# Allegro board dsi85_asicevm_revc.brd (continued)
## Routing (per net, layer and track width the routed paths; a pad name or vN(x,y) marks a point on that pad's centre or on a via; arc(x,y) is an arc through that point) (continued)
DSI_A0P: length 41.7
  TOP w0.076: U1.H3 36.55,45.15 36.55,44.77 36.44,44.66 36.44,44.27
  TOP w0.127: 36.44,44.27 35.77,43.61 34.85,42.68 34.85,41.36 33.8,40.31 29.96,40.31 29.4,40.88 29.4,41.85 28.99,42.26 28.41,42.26 28,41.85 28,40.88 27.43,40.31 26.66,40.31 23.22,43.75 23.22,44.55 23.86,45.19 23.86,45.77 23.46,46.18 22.88,46.18 22.23,45.53 21.43,45.53 20.87,46.1 20.87,46.9 21.51,47.54 21.51,48.2 21.18,48.53 20.52,48.53 19.88,47.89 19.08,47.89 15.49,51.48 12.28,51.48 12.17,51.37 J4.33
  vias: v2(12.18,51.37)
DSI_A1N: length 42.4
  TOP w0.076: U1.J4 36.8,43.63
  TOP w0.127: J4.27 12.15,48.87 12.27,48.75 13.58,48.75 13.76,48.57 13.87,48.57 13.9,48.59 14,48.59 14.08,48.52 14.08,48.41 14.05,48.39 14.05,48.28 14.12,48.21 14.23,48.21 14.26,48.23 14.36,48.23 14.43,48.16 14.43,48.05 14.41,48.03 14.41,47.92 14.48,47.85 14.59,47.85 14.61,47.88 14.72,47.88 14.79,47.8 14.79,47.7 14.77,47.67 14.77,47.56 14.84,47.49 14.95,47.49 14.97,47.52 15.08,47.52 15.15,47.44 15.15,47.34 15.13,47.31 15.13,47.2 15.2,47.13 15.31,47.13 15.33,47.16 15.44,47.16 15.51,47.08 15.51,46.98 15.49,46.95 15.49,46.85 15.56,46.77 15.67,46.77 15.69,46.8 15.8,46.8 15.87,46.72 15.87,46.62 15.85,46.59 15.85,46.49 15.92,46.41 16.02,46.41 16.05,46.44 16.16,46.44 16.23,46.36 16.23,46.26 16.2,46.23 16.2,46.13 16.28,46.05 16.38,46.05 16.41,46.08 16.52,46.08 16.59,46 16.59,45.9 16.56,45.87 16.56,45.77 16.7,45.63 16.9,45.63 17.08,45.46 17.08,45.25 17.38,44.95 17.96,44.95 18.37,45.37 18.53,45.53 19.49,45.53 19.9,45.12 19.9,44.16 19.74,44 19.32,43.59 19.32,43.01 19.73,42.6 20.31,42.6 20.73,43.02 20.88,43.17 21.72,43.17 22.25,42.64 22.25,41.81 22.09,41.65 21.68,41.23 21.68,40.66 23.49,38.84 24.09,38.84 24.63,39.38 25.88,39.38 26.43,38.84 27.41,38.84 27.96,39.38 29.21,39.38 29.75,38.84 30.74,38.84 31.28,39.38 32.54,39.38 33.08,38.84 34.24,38.84 36,40.6 36,42.03 36.8,42.83 36.8,43.63
  vias: v2(12.19,48.87)
DSI_A1P: length 41.8
  TOP w0.076: 37.05,44.22 37.05,45.15 U1.H4
  TOP w0.127: 37.05,44.22 37.07,44.2 37.07,42.72 36.27,41.92 36.27,40.49 34.35,38.57 32.97,38.57 32.43,39.11 31.39,39.11 30.85,38.57 29.64,38.57 29.1,39.11 28.07,39.11 27.52,38.57 26.32,38.57 25.77,39.11 24.74,39.11 24.2,38.57 23.38,38.57 21.41,40.55 21.41,41.34 21.98,41.92 21.98,42.53 21.61,42.91 20.99,42.91 20.42,42.33 19.62,42.33 19.06,42.9 19.06,43.7 19.63,44.27 19.63,45.01 19.38,45.26 18.64,45.26 18.07,44.69 17.27,44.69 13.47,48.48 12.28,48.48 12.17,48.37 J4.25
  vias: v2(12.19,48.36)
DSI_A2N: length 42.4
  TOP w0.076: 37.94,43.46 37.94,44.57 37.8,44.71 U1.J6
  TOP w0.127: J4.11 12.16,42.87 12.28,42.75 13.05,42.75 13.25,42.55 13.35,42.55 13.4,42.6 13.5,42.6 13.58,42.53 13.58,42.42 13.53,42.37 13.53,42.27 13.61,42.19 13.71,42.19 13.76,42.24 13.86,42.24 13.94,42.17 13.94,42.06 13.89,42.01 13.89,41.91 13.96,41.83 14.07,41.83 14.12,41.88 14.22,41.88 14.3,41.81 14.3,41.7 14.25,41.65 14.25,41.55 14.32,41.47 14.43,41.47 14.48,41.52 14.58,41.52 14.66,41.45 14.66,41.34 14.61,41.3 14.61,41.19 14.68,41.12 14.79,41.12 14.84,41.16 14.94,41.16 15.02,41.09 15.02,40.98 14.97,40.94 14.97,40.83 15.04,40.76 15.15,40.76 15.19,40.8 15.3,40.8 15.37,40.73 15.37,40.62 15.33,40.58 15.33,40.47 15.44,40.36 15.6,40.36 15.68,40.28 15.68,40.12 20.81,34.99 21.52,34.99 22.38,35.85 23.32,35.85 24.19,34.99 24.85,34.99 25.74,35.88 26.62,35.88 27.51,34.99 28.17,34.99 29,35.82 30.01,35.82 30.84,34.99 34.43,34.99 38.64,39.19 38.64,42.75 37.94,43.46
  vias: v2(12.19,42.87)
DSI_A2P: length 41.8
  TOP w0.076: U1.H6 38.05,45.15 38.05,44.75 38.19,44.61 38.19,44.27
  TOP w0.127: 38.19,44.27 38.19,43.58 38.91,42.86 38.91,39.08 34.54,34.72 30.73,34.72 29.9,35.55 29.11,35.55 28.28,34.72 27.4,34.72 26.51,35.61 25.85,35.61 24.96,34.72 24.3,34.72 24.07,34.72 23.21,35.58 22.49,35.58 21.63,34.72 21.41,34.72 20.7,34.72 12.94,42.48 12.3,42.48 12.19,42.37 J4.9
  vias: v2(12.18,42.37)
DSI_A3N: length 42.4
  TOP w0.076: U1.J7 38.3,44.73 38.4,44.63 38.4,44.47 38.97,43.91
  TOP w0.127: 38.97,43.91 39.75,43.12 39.75,38.19 34.88,33.33 19.86,33.33 16.12,37.07 16.12,37.17 16.17,37.22 16.17,37.32 16.09,37.39 15.99,37.39 15.94,37.35 15.84,37.35 15.76,37.42 15.76,37.53 15.81,37.57 15.81,37.68 15.73,37.75 15.63,37.75 15.58,37.71 15.48,37.71 15.4,37.78 15.4,37.89 15.45,37.93 15.45,38.04 15.37,38.11 15.27,38.11 15.22,38.07 15.12,38.07 15.05,38.14 15.05,38.25 15.09,38.29 15.09,38.4 15.01,38.47 14.91,38.47 14.87,38.43 14.76,38.43 14.69,38.5 14.69,38.61 14.73,38.65 14.73,38.76 14.66,38.83 14.55,38.83 14.51,38.79 14.4,38.79 14.33,38.86 14.33,38.97 14.37,39.01 14.37,39.12 14.3,39.19 14.19,39.19 14.15,39.15 14.04,39.15 13.97,39.22 13.97,39.33 14.01,39.37 14.01,39.48 13.94,39.55 13.83,39.55 13.79,39.51 13.68,39.51 13.44,39.75 12.26,39.75 12.14,39.87 J4.3
  vias: v2(12.17,39.86)
DSI_A3P: length 41.7
  TOP w0.076: U1.H7 38.55,45.15 38.55,44.71 38.88,44.37
  TOP w0.127: 38.88,44.37 40.02,43.23 40.02,38.08 34.99,33.06 19.75,33.06 13.33,39.48 12.28,39.48 12.17,39.37 J4.1
  vias: v2(12.18,39.36)
DSI_ACLKN: length 42.4
  TOP w0.076: U1.J5 37.3,43.62
  TOP w0.127: J4.19 12.16,45.87 12.28,45.75 12.95,45.75 13.13,45.57 13.23,45.57 13.27,45.6 13.38,45.6 13.45,45.53 13.45,45.42 13.41,45.39 13.41,45.28 13.49,45.21 13.59,45.21 13.63,45.24 13.74,45.24 13.81,45.17 13.81,45.07 13.77,45.03 13.77,44.92 13.85,44.85 13.95,44.85 13.99,44.89 14.09,44.89 14.17,44.81 14.17,44.71 14.13,44.67 14.13,44.56 14.21,44.49 14.31,44.49 14.35,44.53 14.45,44.53 14.53,44.45 14.53,44.35 14.49,44.31 14.49,44.2 14.57,44.13 14.67,44.13 14.71,44.17 14.81,44.17 14.89,44.09 14.89,43.99 14.85,43.95 14.85,43.85 14.92,43.77 15.03,43.77 15.07,43.81 15.17,43.81 15.25,43.73 15.25,43.63 15.21,43.59 15.21,43.49 15.28,43.41 15.39,43.41 15.43,43.45 15.53,43.45 15.61,43.37 15.61,43.27 15.57,43.23 15.57,43.13 15.69,43.01 15.81,43.01 15.91,42.91 15.91,42.79 16.84,41.86 17.42,41.86 17.64,42.09 18.4,42.09 19.01,41.48 19.01,40.72 18.78,40.49 18.78,39.92 19.19,39.51 19.77,39.51 20,39.73 20.8,39.73 21.36,39.17 21.36,38.37 21.13,38.14 21.13,37.56 21.77,36.93 22.19,36.93 22.93,37.67 23.96,37.67 24.7,36.93 25.51,36.93 26.26,37.67 27.29,37.67 28.03,36.93 28.84,36.93 29.6,37.69 30.6,37.69 31.36,36.93 34.17,36.93 37.3,40.06 37.3,43.62
  vias: v2(12.19,45.86)
DSI_ACLKP: length 41.8
  TOP w0.076: U1.H5 37.55,45.15 37.55,44.8 37.55,44.8 37.55,44.23
  TOP w0.127: 37.55,44.23 37.57,44.21 37.57,39.95 34.28,36.66 31.25,36.66 30.49,37.42 29.71,37.42 28.95,36.66 27.92,36.66 27.18,37.41 26.37,37.41 25.62,36.66 24.59,36.66 23.85,37.41 23.04,37.41 22.3,36.66 21.66,36.66 20.87,37.45 20.87,38.25 21.09,38.48 21.09,39.06 20.68,39.47 20.11,39.47 19.88,39.24 19.08,39.24 18.51,39.8 18.51,40.6 18.74,40.83 18.74,41.37 18.29,41.82 17.75,41.82 17.53,41.59 16.73,41.59 12.84,45.48 12.27,45.48 12.15,45.37 J4.17
  vias: v2(12.18,45.36)
DSI_B0N: length 42.1
  TOP w0.127: J4.36 5.38,51.88 v1(3.71,51.88) ; U1.C1 v2(34.79,48.22)
  L3_SIG w0.076: 32.77,49.49 34.04,48.22 v2(34.79,48.22)
  L3_SIG w0.127: v1(3.71,51.88) 3.89,51.77 4.35,51.77 4.43,51.84 4.43,51.96 4.5,52.03 4.61,52.03 4.68,51.96 4.68,51.84 4.76,51.77 4.86,51.77 4.93,51.84 4.93,51.96 5.01,52.03 5.11,52.03 5.19,51.96 5.19,51.84 5.26,51.77 5.37,51.77 5.44,51.84 5.44,51.96 5.52,52.03 5.62,52.03 5.7,51.96 5.7,51.84 5.77,51.77 5.88,51.77 5.95,51.84 5.95,51.96 6.03,52.03 6.13,52.03 6.2,51.96 6.2,51.84 6.28,51.77 6.38,51.77 6.46,51.84 6.46,51.96 6.53,52.03 6.64,52.03 6.71,51.96 6.71,51.84 6.79,51.77 10.63,51.77 11.68,50.71 15.68,50.71 18.8,53.83 19.71,53.83 20.12,54.24 20.12,54.55 20.71,55.13 21.54,55.13 22.13,54.55 22.13,54.24 22.54,53.83 23.12,53.83 23.53,54.24 23.53,54.55 24.11,55.13 24.95,55.13 25.53,54.55 25.53,54.24 25.94,53.83 27.86,53.83 31.46,50.23 32.03,50.23 32.77,49.49 32.77,49.49
DSI_B0P: length 41.5
  TOP w0.076: 35.79,47.9 U1.C2
  TOP w0.127: v1(3.71,51.35) 5.38,51.35 J4.34 ; U1.C2 v2(36.08,47.68)
  L3_SIG w0.076: 33.72,48.11 33.93,47.9 35.09,47.9 35.31,47.68 v2(36.08,47.68)
  L3_SIG w0.127: v1(3.71,51.35) 3.89,51.46 10.5,51.46 11.56,50.41 15.81,50.41 18.92,53.52 19.84,53.52 20.43,54.11 20.43,54.42 20.84,54.83 21.42,54.83 21.82,54.42 21.82,54.11 22.41,53.52 23.24,53.52 23.83,54.11 23.83,54.42 24.24,54.83 24.82,54.83 25.23,54.42 25.23,54.11 25.82,53.52 27.74,53.52 31.34,49.92 31.91,49.92 32.46,49.36 32.46,49.36 33.72,48.11 33.72,48.11
DSI_B1N: length 42.3
  TOP w0.127: v1(3.71,48.88) 5.38,48.88 J4.28 ; U1.D1 v2(34.79,47.59)
  L3_SIG w0.076: 32.26,47.59 34.79,47.59 v2(34.79,47.59)
  L3_SIG w0.127: 32.26,47.59 31.77,47.59 29.32,50.04 24.47,50.04 23.89,49.45 23.89,48.68 23.48,48.27 22.9,48.27 22.49,48.68 22.49,49.45 21.9,50.04 21.07,50.04 20.48,49.45 20.48,48.68 20.07,48.27 19.49,48.27 19.08,48.68 19.08,49.45 18.5,50.04 17.16,50.04 15.07,47.94 11.75,47.94 10.92,48.77 7.81,48.77 7.73,48.84 7.73,48.92 7.66,49 7.55,49 7.48,48.92 7.48,48.84 7.4,48.77 7.3,48.77 7.22,48.84 7.22,48.92 7.15,49 7.04,49 6.97,48.92 6.97,48.84 6.89,48.77 6.79,48.77 6.72,48.84 6.72,48.92 6.64,49 6.54,49 6.46,48.92 6.46,48.84 6.39,48.77 6.28,48.77 6.21,48.84 6.21,48.92 6.13,49 6.03,49 5.95,48.92 5.95,48.84 5.88,48.77 5.77,48.77 5.7,48.84 5.7,48.92 5.62,49 5.52,49 5.45,48.92 5.45,48.84 5.37,48.77 5.27,48.77 5.19,48.84 5.19,48.92 5.12,49 5.01,49 4.94,48.92 4.94,48.84 4.86,48.77 4.76,48.77 4.68,48.84 4.68,48.92 4.61,49 4.5,49 4.43,48.92 4.43,48.84 4.35,48.77 3.89,48.77 v1(3.71,48.88)
DSI_B1P: length 41.7
  TOP w0.127: U1.D2 v2(36.2,47.18) ; J4.26 5.38,48.35 v1(3.71,48.35)
  L3_SIG w0.076: v2(36.2,47.18) 35.85,47.18 35.74,47.28 33.71,47.28
  L3_SIG w0.127: v1(3.71,48.35) 3.89,48.46 10.79,48.46 11.62,47.63 15.19,47.63 17.29,49.73 18.37,49.73 18.78,49.32 18.78,48.56 19.37,47.97 20.2,47.97 20.79,48.56 20.79,49.32 21.2,49.73 21.77,49.73 22.18,49.32 22.18,48.56 22.77,47.97 23.6,47.97 24.19,48.56 24.19,49.32 24.6,49.73 29.2,49.73 31.65,47.28 33.71,47.28
DSI_B2N: length 42.4
  TOP w0.127: U1.F1 v2(34.79,46.34) ; J4.12 5.38,42.88 v1(3.71,42.88)
  L3_SIG w0.076: 32.29,46.27 34.38,46.27 34.45,46.34 v2(34.79,46.34)
  L3_SIG w0.127: v1(3.71,42.88) 3.91,42.75 4.33,42.75 4.4,42.82 4.4,42.93 4.48,43 4.58,43 4.66,42.93 4.66,42.82 4.73,42.75 4.84,42.75 4.91,42.82 4.91,42.93 4.99,43 5.09,43 5.17,42.93 5.17,42.82 5.24,42.75 5.35,42.75 5.42,42.82 5.42,42.93 5.49,43 5.6,43 5.67,42.93 5.67,42.82 5.75,42.75 5.85,42.75 5.93,42.82 5.93,42.93 6,43 6.11,43 6.18,42.93 6.18,42.82 6.26,42.75 6.36,42.75 6.44,42.82 6.44,42.93 6.51,43 6.62,43 6.69,42.93 6.69,42.82 6.76,42.75 6.87,42.75 6.94,42.82 6.94,42.93 7.02,43 7.12,43 7.2,42.93 7.2,42.82 7.27,42.75 10.9,42.75 12.61,41.04 12.99,41.04 13.4,41.45 13.4,41.72 13.99,42.31 14.82,42.31 15.41,41.72 15.41,41.45 15.81,41.04 16.39,41.04 16.8,41.45 16.8,41.72 17.39,42.31 18.22,42.31 18.81,41.72 18.81,41.45 19.22,41.04 19.8,41.04 20.21,41.45 20.21,41.72 20.79,42.31 21.63,42.31 22.21,41.72 22.21,41.45 22.62,41.04 25.89,41.04 30.59,45.74 31.12,46.27 32.29,46.27
DSI_B2P: length 41.8
  TOP w0.127: v1(3.71,42.35) 5.38,42.35 J4.10 ; U1.F2 v2(36.2,46.18)
  L3_SIG w0.076: 33.74,45.96 34.49,45.96 34.56,46.03 35.66,46.03 35.81,46.18 v2(36.2,46.18)
  L3_SIG w0.127: 33.74,45.96 31.24,45.96 26.01,40.74 22.5,40.74 21.91,41.32 21.91,41.6 21.5,42.01 20.92,42.01 20.51,41.6 20.51,41.32 19.92,40.74 19.09,40.74 18.5,41.32 18.5,41.6 18.1,42.01 17.52,42.01 17.11,41.6 17.11,41.32 16.52,40.74 15.69,40.74 15.1,41.32 15.1,41.6 14.69,42.01 14.11,42.01 13.7,41.6 13.7,41.32 13.12,40.74 12.48,40.74 10.77,42.44 3.87,42.44 v1(3.71,42.35)
DSI_B3N: length 42.2
  TOP w0.127: U1.G1 v2(34.79,45.71) ; v1(3.71,39.88) 5.38,39.88 J4.4
  L3_SIG w0.076: 32.8,44.36 34.15,45.71 v2(34.79,45.71)
  L3_SIG w0.127: 32.8,44.36 32.43,43.99 31.67,43.99 25.48,37.8 22.11,37.8 21.7,38.21 21.7,38.3 21.11,38.88 20.28,38.88 19.69,38.3 19.69,38.21 19.28,37.8 18.7,37.8 18.3,38.21 18.3,38.3 17.71,38.88 16.88,38.88 16.29,38.3 16.29,38.21 15.88,37.8 15.3,37.8 14.89,38.21 14.89,38.3 14.3,38.88 13.47,38.88 12.89,38.3 12.89,38.21 12.45,37.77 11.47,37.77 9.47,39.77 7.23,39.77 7.16,39.85 7.16,39.93 7.08,40.01 6.98,40.01 6.91,39.93 6.91,39.85 6.83,39.77 6.73,39.77 6.65,39.85 6.65,39.93 6.58,40.01 6.47,40.01 6.4,39.93 6.4,39.85 6.32,39.77 6.22,39.77 6.14,39.85 6.14,39.93 6.07,40.01 5.96,40.01 5.89,39.93 5.89,39.85 5.81,39.77 5.71,39.77 5.64,39.85 5.64,39.93 5.56,40.01 5.46,40.01 5.38,39.93 5.38,39.85 5.31,39.77 5.2,39.77 5.13,39.85 5.13,39.93 5.05,40.01 4.95,40.01 4.87,39.93 4.87,39.85 4.8,39.77 4.69,39.77 4.62,39.85 4.62,39.93 4.54,40.01 4.44,40.01 4.37,39.93 4.37,39.85 4.29,39.77 3.88,39.77 v1(3.71,39.88)
DSI_B3P: length 41.7
  TOP w0.127: U1.G2 v2(36.08,45.68) ; v1(3.71,39.35) 5.38,39.35 J4.2
  L3_SIG w0.076: 33.84,44.98 34.27,45.4 35.31,45.4 35.59,45.68 v2(36.08,45.68)
  L3_SIG w0.127: v1(3.71,39.35) 3.89,39.47 9.34,39.47 11.34,37.47 12.57,37.47 13.19,38.08 13.19,38.17 13.6,38.58 14.18,38.58 14.59,38.17 14.59,38.08 15.18,37.5 16.01,37.5 16.59,38.08 16.59,38.17 17,38.58 17.58,38.58 17.99,38.17 17.99,38.08 18.58,37.5 19.41,37.5 20,38.08 20,38.17 20.41,38.58 20.99,38.58 21.39,38.17 21.39,38.08 21.98,37.5 25.61,37.5 31.8,43.69 32.56,43.69 33.84,44.97 33.84,44.98
DSI_BCLKN: length 42.4
  TOP w0.127: U1.E1 v2(34.79,46.97) ; v1(3.71,45.88) 5.38,45.88 J4.20
  L3_SIG w0.076: 33.21,46.96 34.78,46.96 v2(34.79,46.97)
  L3_SIG w0.127: 33.21,46.96 25.98,46.96 23.36,44.33 22.33,44.33 22.16,44.5 22.16,45.11 21.57,45.7 20.75,45.7 20.16,45.11 20.16,44.5 19.75,44.09 19.17,44.09 18.76,44.5 18.76,45.11 18.17,45.7 17.34,45.7 16.75,45.11 16.75,44.5 16.34,44.09 15.77,44.09 15.36,44.5 15.36,45.11 14.91,45.55 13.79,45.55 13.35,45.11 13.35,44.68 13.04,44.37 11.99,44.37 10.6,45.76 7.23,45.76 7.16,45.84 7.16,45.92 7.08,45.99 6.98,45.99 6.91,45.92 6.91,45.84 6.83,45.76 6.73,45.76 6.65,45.84 6.65,45.92 6.58,45.99 6.47,45.99 6.4,45.92 6.4,45.84 6.32,45.76 6.22,45.76 6.14,45.84 6.14,45.92 6.07,45.99 5.96,45.99 5.89,45.92 5.89,45.84 5.81,45.76 5.71,45.76 5.64,45.84 5.64,45.92 5.56,45.99 5.46,45.99 5.38,45.92 5.38,45.84 5.31,45.76 5.2,45.76 5.13,45.84 5.13,45.92 5.05,45.99 4.95,45.99 4.87,45.92 4.87,45.84 4.8,45.76 4.69,45.76 4.62,45.84 4.62,45.92 4.54,45.99 4.44,45.99 4.37,45.92 4.37,45.84 4.29,45.76 3.89,45.76 v1(3.71,45.88)
DSI_BCLKP: length 41.8
  TOP w0.127: J4.18 5.38,45.35 v1(3.71,45.35) ; U1.E2 v2(36.08,46.68)
  L3_SIG w0.076: v2(36.08,46.68) 35.57,46.68 35.55,46.65 33.53,46.65
  L3_SIG w0.127: v1(3.71,45.35) 3.89,45.46 10.47,45.46 11.86,44.07 13.17,44.07 13.66,44.56 13.66,44.98 13.92,45.25 14.79,45.25 15.05,44.98 15.05,44.38 15.64,43.79 16.47,43.79 17.06,44.38 17.06,44.98 17.47,45.39 18.05,45.39 18.46,44.98 18.46,44.38 19.04,43.79 19.87,43.79 20.46,44.38 20.46,44.98 20.88,45.4 21.45,45.4 21.86,44.98 21.86,44.38 22.21,44.03 23.48,44.03 26.11,46.65 33.53,46.65
EN1P8: length 3.4
  TOP w0.356: C47.1 40.77,65.74 R87.2 39.55,65.76 U9.11
EN3P3: length 3.2
  TOP w0.356: U8.11 44.76,77.28 R79.2 46.05,77.19 C43.1
EXT_BKLT_9V: length 20.1
  TOP w0.762: FB6.2 59.33,91.18 59.34,91.19 Q1.4
  TOP w1.016: TP4.1 55.19,98.94 55.19,91.93 56.55,90.56 57.31,90.56 R91.2 58.6,90.58 58.64,90.62 FB6.2 59.46,90.62 61.05,92.22 C49.1 63.25,92.22 63.59,91.88 R92.2
EXT_REFCLK: length 8.3
  L3_SIG w0.254: J17.1 36.78,37.45 v1(36.78,40.38)
  BOTTOM w0.356: R105.1 v1(36.78,40.38)
FB_1PT8V: length 3.4
  TOP w0.356: R90.2 37.26,71.7 R89.1 36.3,71.57 U9.16
FB_3PT3V: length 3.3
  TOP w0.356: R84.2 42.81,83.09 R82.1 41.74,82.99 U8.16
FLATA_20455_CLKN: length 59.3
  TOP w0.14: v3(89.45,77.41) 89.11,77.41 89.09,77.43 J2.17
  BOTTOM w0.127: v3(89.45,77.41) 89.35,77.32 83.75,77.32 74.59,68.17 74.59,64.86 74.19,64.45 72.08,64.45 71.51,63.88 71.51,63.08 72.08,62.52 74.19,62.52 74.59,62.11 74.59,61.53 74.19,61.12 72.08,61.12 71.5,60.54 71.5,59.77 72.08,59.19 74.19,59.19 74.59,58.78 74.59,56.7 71.7,53.81 68.05,53.81 66.7,52.45 66.7,50.27 64.02,47.6 61.87,47.6 61.72,47.6 R23.2
FLATA_20455_CLKP: length 59.3
  TOP w0.14: v3(89.45,76.96) 89.11,76.96 89.09,76.93 J2.18
  BOTTOM w0.127: R24.2 61.72,47.33 64.13,47.33 66.96,50.16 66.96,52.34 68.16,53.54 71.81,53.54 74.86,56.59 74.86,58.89 74.3,59.46 72.19,59.46 71.77,59.88 71.77,60.43 72.19,60.85 74.3,60.85 74.86,61.42 74.86,62.22 74.3,62.78 72.19,62.78 71.78,63.19 71.78,63.77 72.19,64.18 74.3,64.18 74.86,64.75 74.86,68.05 83.86,77.05 89.35,77.05 v3(89.45,76.96)
FLATA_20455_YN0: length 59.3
  TOP w0.14: v3(89.45,81.91) 89.11,81.91 89.09,81.93 J2.8
  BOTTOM w0.127: v3(89.45,81.91) 89.11,81.91 89.01,81.82 83.05,81.82 70.64,69.41 61.96,69.41 56.59,64.04 56.59,54.55 57.84,53.31 62.29,53.31 62.75,52.84 62.75,52.51 62.35,52.11 61.71,52.11 R17.2
FLATA_20455_YN1: length 59.3
  TOP w0.14: J2.11 89.09,80.43 89.11,80.41 v3(89.45,80.41)
  BOTTOM w0.127: v3(89.45,80.41) 89.35,80.32 83.25,80.32 71.16,68.23 62.28,68.23 57.72,63.66 57.72,55.44 58.76,54.4 62.64,54.4 63.75,53.29 63.75,51.27 63.07,50.6 62.11,50.6 61.99,50.6 61.72,50.6 R19.2
FLATA_20455_YN2: length 59.3
  TOP w0.14: v3(89.45,78.91) 89.11,78.91 89.09,78.93 J2.14
  BOTTOM w0.127: v3(89.45,78.91) 89.35,78.82 83.59,78.82 71.56,66.79 62.77,66.79 58.83,62.84 58.83,57.11 60.55,55.39 63.39,55.39 65.67,53.11 65.67,51.34 63.44,49.11 61.72,49.11 R21.2
FLATA_20455_YN3: length 59.3
  TOP w0.14: v3(89.45,75.91) 89.11,75.91 89.09,75.93 J2.20
  BOTTOM w0.127: v3(89.45,75.91) 89.35,75.82 84.03,75.82 75.97,67.76 75.97,62.53 76.54,61.97 78.51,61.97 78.92,61.56 78.92,60.98 78.51,60.57 76.54,60.57 75.97,60 75.97,59.2 76.54,58.64 78.51,58.64 78.92,58.23 78.92,57.65 78.51,57.24 76.54,57.24 75.97,56.68 75.97,55.94 73.07,53.04 68.44,53.04 67.65,52.25 67.65,49.45 64.3,46.1 61.72,46.1 R26.2
FLATA_20455_YP0: length 59.3
  TOP w0.14: J2.9 89.09,81.43 89.11,81.46 v3(89.45,81.46)
  BOTTOM w0.127: R18.2 61.73,51.84 61.99,51.84 61.99,51.84 62.46,51.84 63.02,52.4 63.02,52.95 62.4,53.57 57.95,53.57 56.86,54.66 56.86,63.93 62.07,69.14 70.75,69.14 83.16,81.55 89.01,81.55 89.11,81.46 v3(89.45,81.46)
FLATA_20455_YP1: length 59.3
  TOP w0.14: v3(89.45,79.96) 89.11,79.96 89.09,79.93 J2.12
  BOTTOM w0.127: R20.2 61.71,50.33 61.98,50.33 62.11,50.33 63.18,50.33 64.02,51.16 64.02,53.4 62.75,54.67 58.87,54.67 57.99,55.55 57.99,63.55 62.39,67.96 71.27,67.96 83.36,80.05 89.35,80.05 v3(89.45,79.96)
FLATA_20455_YP2: length 59.3
  TOP w0.14: J2.15 89.09,78.43 89.11,78.46 v3(89.45,78.46)
  BOTTOM w0.127: v3(89.45,78.46) 89.35,78.55 83.7,78.55 71.67,66.52 62.88,66.52 59.09,62.73 59.09,57.22 60.66,55.65 63.5,55.65 65.93,53.22 65.93,51.23 63.55,48.84 61.73,48.84 R22.2
FLATA_20455_YP3: length 59.3
  TOP w0.14: v3(89.45,75.46) 89.11,75.46 89.09,75.43 J2.21
  BOTTOM w0.127: v3(89.45,75.46) 89.35,75.55 84.14,75.55 76.24,67.65 76.24,62.64 76.65,62.23 78.62,62.23 79.18,61.67 79.18,60.87 78.62,60.3 76.65,60.3 76.24,59.89 76.24,59.31 76.65,58.9 78.62,58.9 79.18,58.34 79.18,57.54 78.62,56.97 76.65,56.97 76.24,56.57 76.24,55.83 73.18,52.77 68.55,52.77 67.92,52.14 67.92,49.34 64.41,45.84 61.72,45.84 R25.2
FLATB_20455_CLKN: length 22.2
  TOP w0.14: J5.17 89.09,44.41 89.11,44.39 v3(89.45,44.39)
  BOTTOM w0.127: v3(89.45,44.39) 89.35,44.3 80.39,44.3 77.09,47.6 69.85,47.6 R45.2
FLATB_20455_CLKP: length 22.2
  TOP w0.14: J5.18 89.09,43.91 89.12,43.94 89.44,43.94 v3(89.45,43.94)
  BOTTOM w0.127: R46.2 69.85,47.33 76.98,47.33 80.28,44.03 89.35,44.03 v3(89.45,43.94)
FLATB_20455_YN0: length 22.2
  TOP w0.14: v3(89.45,48.89) 89.39,48.94 89.1,48.94 89.07,48.91 J5.8
  BOTTOM w0.127: v3(89.45,48.89) 89.35,48.8 83.55,48.8 80.24,52.1 69.87,52.1 R42.2
FLATB_20455_YN1: length 22.2
  TOP w0.14: v3(89.45,47.39) 89.11,47.39 89.09,47.41 J5.11
  BOTTOM w0.127: v3(89.45,47.39) 89.35,47.3 82.51,47.3 79.19,50.62 69.85,50.62 R40.2
FLATB_20455_YN2: length 22.2
  TOP w0.14: J5.14 89.09,45.91 89.11,45.89 v3(89.45,45.89)
  BOTTOM w0.127: v3(89.45,45.89) 89.35,45.8 81.45,45.8 78.14,49.11 69.85,49.11 R44.2
FLATB_20455_YN3: length 22.2
  TOP w0.14: J5.20 89.09,42.91 89.11,42.89 v3(89.45,42.89)
  BOTTOM w0.127: R47.2 69.87,46.11 76.26,46.11 79.57,42.8 89.35,42.8 v3(89.45,42.89)
FLATB_20455_YP0: length 22.2
  TOP w0.14: J5.9 89.09,48.41 89.11,48.39 89.4,48.39 v3(89.45,48.44)
  BOTTOM w0.127: v3(89.45,48.44) 89.35,48.53 83.44,48.53 80.13,51.84 69.87,51.84 R39.2
FLATB_20455_YP1: length 22.2
  TOP w0.14: J5.12 89.42,46.91 v3(89.45,46.94)
  BOTTOM w0.127: v3(89.45,46.94) 89.35,47.03 82.4,47.03 79.08,50.35 69.86,50.35 69.75,50.24 R41.2
FLATB_20455_YP2: length 22.2
  TOP w0.14: J5.15 89.09,45.41 89.11,45.44 v3(89.45,45.44)
  BOTTOM w0.127: v3(89.45,45.44) 89.35,45.53 81.34,45.53 78.03,48.84 69.87,48.84 R43.2
FLATB_20455_YP3: length 22.2
  TOP w0.14: v3(89.45,42.44) 89.44,42.44 89.12,42.44 89.09,42.41 J5.21
  BOTTOM w0.127: R48.2 69.87,45.84 76.15,45.84 79.46,42.53 89.35,42.53 v3(89.45,42.44)
FLATCHA_CLKN: length 47.1
  TOP w0.076: U1.F9 40.59,46.4 40.61,46.42
  TOP w0.127: J6.13 62.05,47.73 v3(60.53,47.73) 60.42,47.61 59.64,47.61 59.56,47.68 59.56,47.72 59.49,47.8 59.38,47.8 59.31,47.72 59.31,47.68 59.24,47.61 59.13,47.61 59.06,47.68 59.06,47.72 58.98,47.8 58.88,47.8 58.8,47.72 58.8,47.68 58.73,47.61 58.62,47.61 58.55,47.68 58.55,47.72 58.47,47.8 58.37,47.8 58.29,47.72 58.29,47.68 58.22,47.61 58.11,47.61 58.04,47.68 58.04,47.72 57.97,47.8 57.86,47.8 57.79,47.72 57.79,47.68 57.71,47.61 57.61,47.61 57.53,47.68 57.53,47.72 57.46,47.8 57.35,47.8 57.28,47.72 57.28,47.68 57.2,47.61 57.1,47.61 57.02,47.68 57.02,47.72 56.95,47.8 56.84,47.8 56.77,47.72 56.77,47.68 56.7,47.61 56.32,47.61 54.91,49.02 54.91,51.65 54.35,52.21 53.55,52.21 52.98,51.65 52.98,45.04 52.56,44.62 52.02,44.62 51.58,45.05 51.58,51.65 51.43,51.8 51.02,52.21 50.22,52.21 49.65,51.65 49.65,48.52 49.25,48.11 48.24,48.11 45.59,45.46 42.13,45.46 41.17,46.42 40.61,46.42
  BOTTOM w0.127: R23.1 60.54,47.72 v3(60.53,47.73)
FLATCHA_CLKP: length 46.4
  TOP w0.076: U1.F8 39.05,46.15 39.97,46.15
  TOP w0.127: J6.15 62.05,47.22 62.05,47.22 v3(60.53,47.22) 60.41,47.34 56.21,47.34 54.65,48.91 54.65,51.54 54.24,51.95 53.66,51.95 53.25,51.54 53.25,44.93 52.67,44.35 51.91,44.35 51.32,44.94 51.32,51.54 50.91,51.95 50.33,51.95 49.92,51.54 49.92,48.41 49.36,47.85 48.35,47.85 45.7,45.19 42.02,45.19 41.06,46.15 39.97,46.15
  BOTTOM w0.127: v3(60.53,47.22) 60.53,47.22 R24.1
FLATCHA_Y0N: length 47.1
  TOP w0.076: 40.39,48.47 40.31,48.38 40.31,48.38 39.83,47.9 U1.C9
  TOP w0.127: 40.39,48.47 40.94,49.01 43.51,49.01 44.01,49.51 44.01,52.35 42.08,54.27 42.08,59.61 44.27,61.79 48.7,61.79 49.53,60.97 58.16,60.97 59.71,59.42 59.71,55.92 59.78,55.84 59.84,55.84 59.91,55.77 59.91,55.66 59.84,55.59 59.78,55.59 59.71,55.52 59.71,55.41 59.78,55.34 59.84,55.34 59.91,55.26 59.91,55.16 59.84,55.08 59.78,55.08 59.71,55.01 59.71,54.9 59.78,54.83 59.84,54.83 59.91,54.75 59.91,54.65 59.84,54.57 59.78,54.57 59.71,54.5 59.71,54.39 59.78,54.32 59.84,54.32 59.91,54.25 59.91,54.14 59.84,54.07 59.78,54.07 59.71,53.99 59.71,53.89 59.78,53.81 59.84,53.81 59.91,53.74 59.91,53.63 59.84,53.56 59.78,53.56 59.71,53.48 59.71,53.38 59.78,53.3 59.84,53.3 59.91,53.23 59.91,53.12 59.84,53.05 59.78,53.05 59.71,52.98 59.71,52.61 60.22,52.1 60.4,52.1 60.52,52.22 v3(60.53,52.22) 62.05,52.22 J6.1
  BOTTOM w0.127: R17.1 60.53,52.22 v3(60.53,52.22)
FLATCHA_Y0P: length 46.3
  TOP w0.076: 39.96,47.65 39.05,47.65 U1.C8
  TOP w0.127: 39.96,47.65 41.05,48.75 43.62,48.75 44.28,49.4 44.28,52.46 42.35,54.38 42.35,59.5 44.38,61.52 48.59,61.52 49.41,60.7 58.05,60.7 59.44,59.31 59.44,52.5 60.11,51.83 60.43,51.83 60.54,51.72 v3(60.54,51.72) 62.05,51.72 J6.3
  BOTTOM w0.127: R18.1 v3(60.54,51.72)
FLATCHA_Y1N: length 47
  TOP w0.076: U1.D9 40.69,47.4
  TOP w0.127: J6.5 62.04,50.71 v3(60.53,50.71) 60.42,50.6 59.92,50.6 59.73,50.79 59.73,50.9 59.79,50.96 59.79,51.06 59.72,51.14 59.61,51.14 59.55,51.07 59.44,51.07 59.37,51.15 59.37,51.25 59.43,51.32 59.43,51.42 59.36,51.5 59.25,51.5 59.19,51.43 59.08,51.43 59.01,51.51 59.01,51.61 59.07,51.68 59.07,51.78 59,51.86 58.89,51.86 58.83,51.79 58.72,51.79 58.65,51.87 58.65,51.97 58.71,52.03 58.71,52.14 58.64,52.21 58.53,52.21 58.47,52.15 58.37,52.15 58.18,52.34 58.18,57.43 56.12,59.49 54.69,59.49 54.12,58.92 54.12,58.84 53.71,58.43 53.13,58.43 52.73,58.84 52.73,58.92 52.16,59.49 51.36,59.49 50.79,58.92 50.79,58.84 50.39,58.43 49.81,58.43 49.4,58.84 49.4,58.92 48.64,59.68 47.79,59.68 47.3,60.17 45.34,60.17 43.44,58.27 43.44,54.75 45.58,52.61 45.58,49.16 44.35,47.94 41.23,47.94 40.69,47.4
  BOTTOM w0.127: R19.1 v3(60.54,50.72)
FLATCHA_Y1P: length 46.4
  TOP w0.076: 39.96,47.15 39.05,47.15 U1.D8
  TOP w0.127: J6.7 v3(60.53,50.22) 60.5,50.25 60.49,50.25 60.4,50.33 59.81,50.33 57.91,52.23 57.91,57.32 56.01,59.22 54.8,59.22 54.39,58.81 54.39,58.73 53.82,58.17 53.02,58.17 52.46,58.73 52.46,58.81 52.05,59.22 51.47,59.22 51.06,58.81 51.06,58.73 50.5,58.17 49.7,58.17 49.13,58.73 49.13,58.81 48.53,59.41 47.68,59.41 47.19,59.9 45.45,59.9 43.71,58.16 43.71,54.86 45.84,52.72 45.84,49.05 44.46,47.67 41.34,47.67 40.82,47.15 39.96,47.15
  BOTTOM w0.127: R20.1 60.53,50.22 v3(60.53,50.22)
FLATCHA_Y2N: length 47.1
  TOP w0.076: 40.6,46.91 40.6,46.9 U1.E9
  TOP w0.127: J6.9 62.05,49.23 v3(60.54,49.23) 60.48,49.17 60.44,49.17 60.38,49.11 59.27,49.11 58.93,49.45 58.93,49.55 58.97,49.6 58.97,49.7 58.9,49.78 58.79,49.78 58.75,49.73 58.65,49.73 58.57,49.81 58.57,49.91 58.61,49.95 58.61,50.06 58.54,50.13 58.44,50.13 58.39,50.09 58.29,50.09 58.21,50.17 58.21,50.27 58.26,50.31 58.26,50.42 58.18,50.49 58.08,50.49 58.03,50.45 57.93,50.45 57.85,50.53 57.85,50.63 57.9,50.67 57.9,50.78 57.82,50.85 57.72,50.85 57.67,50.81 57.57,50.81 57.49,50.88 57.49,50.99 57.54,51.03 57.54,51.14 57.46,51.21 57.36,51.21 57.31,51.17 57.21,51.17 56.89,51.49 56.89,56.16 55.81,57.25 54.67,57.25 54.11,56.68 54.11,56.1 53.7,55.69 53.12,55.69 52.71,56.1 52.71,56.68 52.14,57.25 51.35,57.25 50.78,56.68 50.78,56.1 50.37,55.69 49.79,55.69 49.38,56.1 49.38,56.68 48.82,57.25 48.27,57.25 47.64,57.88 45.86,57.88 44.82,56.83 44.82,55.17 46.86,53.12 46.86,48.65 45.11,46.91 40.6,46.91
  BOTTOM w0.127: v3(60.54,49.23) 60.55,49.22 R21.1
FLATCHA_Y2P: length 46.5
  TOP w0.076: U1.E8 39.05,46.65 39.96,46.65 39.97,46.64
  TOP w0.127: 39.97,46.64 45.22,46.64 47.13,48.54 47.13,53.23 45.08,55.28 45.08,56.72 45.97,57.61 47.53,57.61 48.16,56.98 48.71,56.98 49.12,56.57 49.12,55.99 49.68,55.42 50.48,55.42 51.05,55.99 51.05,56.57 51.46,56.98 52.03,56.98 52.44,56.57 52.44,55.99 53.01,55.42 53.81,55.42 54.37,55.99 54.37,56.57 54.78,56.98 55.7,56.98 56.63,56.05 56.63,51.37 59.16,48.84 60.49,48.84 60.55,48.78 v3(60.55,48.72) 62.05,48.72 62.05,48.72
  BOTTOM w0.127: v3(60.55,48.72) 60.55,48.72 R22.1
FLATCHA_Y3N: length 46.9
  TOP w0.076: 40.54,45.82 40.46,45.9 U1.G9
  TOP w0.127: 40.54,45.82 42.42,43.95 43.55,43.95 44.19,43.31 44.19,37.48 45.03,36.65 45.83,36.65 46.24,37.05 46.24,38.97 46.66,39.39 47.74,39.39 48.17,38.97 48.17,37.05 48.58,36.65 49.16,36.65 49.56,37.05 49.56,38.87 50.07,39.37 51.09,39.37 51.49,38.97 51.49,37.05 51.9,36.65 53.34,36.65 55.81,39.12 55.81,43.05 56.37,43.61 57.27,43.61 57.76,44.1 57.76,44.21 57.72,44.25 57.72,44.35 57.8,44.43 57.9,44.43 57.94,44.39 58.05,44.39 58.12,44.46 58.12,44.57 58.08,44.61 58.08,44.71 58.15,44.79 58.26,44.79 58.3,44.75 58.41,44.75 58.48,44.82 58.48,44.93 58.44,44.97 58.44,45.07 58.51,45.15 58.62,45.15 58.66,45.1 58.77,45.1 58.84,45.18 58.84,45.28 58.8,45.32 58.8,45.43 58.87,45.5 58.98,45.5 59.02,45.46 59.12,45.46 59.2,45.54 59.2,45.64 59.16,45.68 59.16,45.79 59.23,45.86 59.34,45.86 59.38,45.82 59.48,45.82 59.77,46.11 60.42,46.11 v3(60.53,46.22) 62.05,46.23 J6.17
  BOTTOM w0.127: R26.1 60.53,46.22 v3(60.53,46.23)
FLATCHA_Y3P: length 46.4
  TOP w0.076: U1.G8 39.05,45.65 39.98,45.65
  TOP w0.127: 39.98,45.65 40.33,45.65 42.3,43.68 43.44,43.68 43.92,43.2 43.92,37.37 44.91,36.38 45.94,36.38 46.5,36.94 46.5,38.86 46.77,39.13 47.63,39.13 47.9,38.86 47.9,36.94 48.47,36.38 49.27,36.38 49.83,36.94 49.83,38.76 50.18,39.11 50.98,39.11 51.23,38.86 51.23,36.94 51.79,36.38 53.45,36.38 56.08,39.01 56.08,42.94 56.48,43.34 57.38,43.34 59.89,45.85 60.4,45.85 v3(60.53,45.72) 62.05,45.72 62.05,45.72 J6.19
  BOTTOM w0.127: v3(60.53,45.72) 60.53,45.72 R25.1
FLATCHB_CLKN: length 47
  TOP w0.127: v3(69.18,47.71) 69.17,47.72 J6.14 ; v2(37.93,49.41) 37.93,49.05 37.8,48.92 U1.A6
  L3_SIG w0.076: 38.41,51.73 38.41,51.55 37.93,51.07 v2(37.93,49.41)
  L3_SIG w0.127: 38.41,51.73 38.41,51.73 38.41,52.88 40.4,54.87 44.96,54.87 46.19,53.65 47.3,53.65 48.04,52.91 48.04,51.8 48.59,51.24 49.71,51.24 50.45,50.51 50.45,49.39 51,48.84 52.12,48.84 52.85,48.1 52.85,46.98 55.53,44.3 61.69,44.3 63.42,46.03 63.42,46.96 64.08,47.62 66.06,47.62 66.13,47.69 66.13,47.78 66.21,47.85 66.31,47.85 66.39,47.78 66.39,47.69 66.46,47.62 66.57,47.62 66.64,47.69 66.64,47.78 66.71,47.85 66.82,47.85 66.89,47.78 66.89,47.69 66.97,47.62 67.07,47.62 67.15,47.69 67.15,47.78 67.22,47.85 67.33,47.85 67.4,47.78 67.4,47.69 67.48,47.62 67.58,47.62 67.66,47.69 67.66,47.78 67.73,47.85 67.84,47.85 67.91,47.78 67.91,47.69 67.98,47.62 68.09,47.62 68.16,47.69 68.16,47.78 68.24,47.85 68.34,47.85 68.42,47.78 68.42,47.69 68.49,47.62 69.09,47.62 v3(69.18,47.71)
FLATCHB_CLKP: length 46.4
  TOP w0.127: U1.B6 37.8,48.28 v2(38.05,48.03) ; v3(69.18,47.22) 69.18,47.22 67.79,47.22 J6.16
  L3_SIG w0.076: 38.24,50.5 38.24,49.2 38.05,49.01 38.05,48.8 38.05,48.79 v2(38.05,48.03)
  L3_SIG w0.127: v3(69.18,47.22) 69.09,47.31 64.2,47.31 63.72,46.83 63.72,45.9 61.82,44 55.41,44 52.55,46.86 52.55,47.97 51.99,48.53 50.87,48.53 50.14,49.26 50.14,50.38 49.59,50.94 48.47,50.94 47.73,51.67 47.73,52.79 47.18,53.34 46.06,53.34 44.84,54.57 40.53,54.57 38.72,52.76 38.72,51.86 38.72,51.86 38.72,51.43 38.23,50.95 38.23,50.5 38.24,50.5
FLATCHB_Y0N: length 47
  TOP w0.127: U1.A3 36.3,48.91 36.05,49.16 v2(36.05,49.41) ; J6.2 69.19,52.22 v3(69.19,52.22)
  L3_SIG w0.076: v2(36.05,49.41) 36.05,49.73 34.81,50.97 34.81,51.42
  L3_SIG w0.127: v3(69.19,52.22) 69.1,52.12 68.38,52.12 68.38,52.12 66.21,52.12 65.98,52.35 65.98,52.46 66.02,52.5 66.02,52.6 65.95,52.68 65.84,52.68 65.8,52.64 65.7,52.64 65.62,52.71 65.62,52.82 65.66,52.86 65.66,52.96 65.59,53.04 65.48,53.04 65.44,53 65.34,53 65.26,53.07 65.26,53.18 65.3,53.22 65.3,53.32 65.23,53.4 65.12,53.4 65.08,53.36 64.98,53.36 64.9,53.43 64.9,53.53 64.94,53.57 64.94,53.68 64.87,53.75 64.76,53.75 64.72,53.71 64.62,53.71 64.55,53.79 64.55,53.89 64.58,53.93 64.58,54.04 64.51,54.11 64.41,54.11 64.37,54.07 64.26,54.07 64.08,54.25 61.68,54.25 57.52,58.41 39.48,58.41 34.81,53.75 34.81,51.42 34.81,51.42
FLATCHB_Y0P: length 46.4
  TOP w0.127: U1.B3 36.3,48.4 v2(36.55,48.16) ; v3(69.19,51.72) 69.18,51.72 J6.4
  L3_SIG w0.076: v2(36.55,48.16) 36.55,49.01 36.36,49.2 36.36,49.79 35.78,50.38
  L3_SIG w0.127: v3(69.19,51.72) 69.09,51.81 69.07,51.82 68.25,51.82 68.25,51.82 66.09,51.82 65.52,52.38 63.95,53.95 61.55,53.95 57.39,58.11 39.6,58.11 35.11,53.62 35.11,51.54 35.12,51.54 35.12,51.04 35.78,50.38
FLATCHB_Y1N: length 47.1
  TOP w0.127: J6.6 69.18,50.72 v3(69.19,50.72) ; U1.A4 36.8,48.92 36.67,49.05 v2(36.67,49.41)
  L3_SIG w0.076: v2(36.67,49.41) 36.67,50.12 36,50.79 36,51.68
  L3_SIG w0.127: 36,51.68 36,51.68 36,53.48 39.87,57.34 49.64,57.34 50.28,56.71 51.23,56.71 51.87,57.34 53.04,57.34 53.69,56.7 54.62,56.7 55.27,57.34 56.59,57.34 60.81,53.12 63.5,53.12 64.11,52.52 64.11,51.55 65.04,50.62 66.28,50.62 66.35,50.69 66.35,50.78 66.43,50.86 66.53,50.86 66.61,50.78 66.61,50.69 66.68,50.62 66.79,50.62 66.86,50.69 66.86,50.78 66.94,50.86 67.04,50.86 67.12,50.78 67.12,50.69 67.19,50.62 67.3,50.62 67.37,50.69 67.37,50.78 67.44,50.86 67.55,50.86 67.62,50.78 67.62,50.69 67.7,50.62 67.8,50.62 67.88,50.69 67.88,50.78 67.95,50.86 68.06,50.86 68.13,50.78 68.13,50.69 68.21,50.62 68.31,50.62 68.39,50.69 68.39,50.78 68.46,50.86 68.57,50.86 68.64,50.78 68.64,50.69 68.71,50.62 69.06,50.62 69.1,50.63 v3(69.19,50.72)
FLATCHB_Y1P: length 46.4
  TOP w0.127: v2(37.05,48.03) 37.01,48.07 37.01,48.2 36.81,48.4 U1.B4 ; J6.8 69.18,50.22 v3(69.19,50.22)
  L3_SIG w0.076: v2(37.05,48.03) 36.98,48.1 36.98,50.17 36.71,50.44
  L3_SIG w0.127: 36.71,50.44 36.3,50.85 36.3,51.55 36.31,51.55 36.31,51.81 36.3,51.81 36.3,53.35 39.99,57.04 49.51,57.04 50.15,56.4 51.35,56.4 51.99,57.04 52.92,57.04 53.57,56.39 54.75,56.39 55.4,57.04 56.47,57.04 60.69,52.82 63.38,52.82 63.81,52.39 63.81,51.42 64.92,50.31 69.09,50.31 69.19,50.22 v3(69.19,50.22)
FLATCHB_Y2N: length 47
  TOP w0.127: J6.10 69.18,49.22 v3(69.19,49.22) ; U1.A5 v2(37.3,49.41)
  L3_SIG w0.076: v2(37.3,49.41) 37.3,51.97
  L3_SIG w0.127: 37.3,51.97 37.3,53.31 39.89,55.9 47.38,55.9 58.13,45.14 61.11,45.14 62.3,46.33 62.3,47.95 63.46,49.12 65.86,49.12 66.04,49.12 66.12,49.2 66.12,49.25 66.19,49.33 66.3,49.33 66.37,49.25 66.37,49.2 66.45,49.12 66.55,49.12 66.62,49.2 66.62,49.25 66.7,49.33 66.8,49.33 66.88,49.25 66.88,49.2 66.95,49.12 67.06,49.12 67.13,49.2 67.13,49.25 67.21,49.33 67.31,49.33 67.39,49.25 67.39,49.2 67.46,49.12 67.57,49.12 67.64,49.2 67.64,49.25 67.72,49.33 67.82,49.33 67.89,49.25 67.89,49.2 67.97,49.12 68.07,49.12 68.15,49.2 68.15,49.25 68.22,49.33 68.33,49.33 68.4,49.25 68.4,49.2 68.48,49.12 69.02,49.12 69.11,49.14 v3(69.19,49.22)
FLATCHB_Y2P: length 46.5
  TOP w0.127: v3(69.19,48.73) 69.19,48.72 67.79,48.72 ; v2(37.55,48.16) 37.3,48.4 U1.B5
  L3_SIG w0.076: v2(37.55,48.16) 37.61,48.22 37.61,50.67
  L3_SIG w0.127: v3(69.19,48.73) 69.12,48.8 69.03,48.82 63.59,48.82 62.6,47.83 62.6,46.2 61.24,44.84 58.01,44.84 47.26,55.59 40.01,55.59 37.6,53.18 37.6,50.68 37.61,50.67
FLATCHB_Y3N: length 46.9
  TOP w0.127: U1.A7 38.3,48.92 38.55,49.17 v2(38.55,49.41) ; v3(69.19,46.23) 69.19,46.22 67.79,46.22 J6.18
  L3_SIG w0.076: 39.53,51.57 39.53,51.57 39.53,50.55 38.55,49.57 v2(38.55,49.41)
  L3_SIG w0.127: v3(69.19,46.23) 69.09,46.13 68.65,46.13 68.58,46.2 68.58,46.27 68.5,46.34 68.4,46.34 68.32,46.27 68.32,46.2 68.25,46.13 68.14,46.13 68.07,46.2 68.07,46.27 67.99,46.34 67.89,46.34 67.81,46.27 67.81,46.2 67.74,46.13 67.63,46.13 67.56,46.2 67.56,46.27 67.49,46.34 67.38,46.34 67.31,46.27 67.31,46.2 67.23,46.13 67.13,46.13 67.05,46.2 67.05,46.27 66.98,46.34 66.87,46.34 66.8,46.27 66.8,46.2 66.72,46.13 66.62,46.13 66.54,46.2 66.54,46.27 66.47,46.34 66.36,46.34 66.29,46.27 66.29,46.2 66.22,46.13 65.48,46.13 64.54,45.18 64.54,44.37 63.44,43.28 53.53,43.28 51.08,45.73 51.08,46.31 51.23,46.46 51.23,47.29 50.65,47.88 49.81,47.88 49.66,47.73 49.08,47.73 48.67,48.14 48.67,48.71 48.83,48.87 48.83,49.7 48.24,50.29 47.41,50.29 47.25,50.13 46.68,50.13 46.27,50.54 46.27,51.12 46.42,51.27 46.42,52.11 45.83,52.69 45,52.69 44.85,52.54 44.27,52.54 43.18,53.63 40.4,53.63 39.53,52.76 39.53,51.57
FLATCHB_Y3P: length 46.2
  TOP w0.127: v2(38.55,48.16) 38.3,48.4 U1.B7 ; v3(69.19,45.72) 69.19,45.72 67.79,45.72 J6.20
  L3_SIG w0.076: 39.62,50.23 38.89,49.49 38.89,49.31 38.51,48.94 38.51,48.19 v2(38.55,48.16)
  L3_SIG w0.127: 39.62,50.23 39.84,50.45 39.84,52.63 40.53,53.33 43.05,53.33 44.14,52.24 44.97,52.24 45.13,52.39 45.71,52.39 46.12,51.98 46.12,51.4 45.96,51.25 45.96,50.42 46.55,49.83 47.38,49.83 47.53,49.98 48.11,49.98 48.52,49.57 48.52,48.99 48.37,48.84 48.37,48.01 48.96,47.42 49.79,47.42 49.94,47.57 50.52,47.57 50.93,47.17 50.93,46.59 50.78,46.43 50.78,45.6 53.41,42.97 63.57,42.97 64.84,44.25 64.84,45.06 65.61,45.82 69.09,45.82 v3(69.19,45.72)
FX_CLKN: length 64.3
  BOTTOM w0.127: R7.2 12.92,45.7 13.86,45.7 14.28,45.28 14.28,44.46 13.84,44.02 13.14,44.02 13.06,43.95 13.06,43.91 12.99,43.84 12.88,43.84 12.81,43.91 12.81,43.95 12.73,44.02 12.63,44.02 12.55,43.95 12.55,43.91 12.48,43.84 12.37,43.84 12.3,43.91 12.3,43.95 12.22,44.02 11.91,44.02 11.3,43.41 11.3,38.45 15.76,33.99 15.76,27.52 12.03,23.79 12.03,5.99 13.63,4.39 24.32,4.39 25.49,5.57 25.49,7.64 v3(25.23,7.9)
FX_CLKP: length 64.3
  BOTTOM w0.127: R6.2 12.81,45.43 13.75,45.43 14.01,45.17 14.01,44.57 13.73,44.29 11.8,44.29 11.03,43.52 11.03,38.34 15.49,33.88 15.49,27.63 11.77,23.9 11.77,5.87 13.52,4.13 24.43,4.13 25.76,5.46 25.76,7.64 v3(26.03,7.9)
FX_N0: length 64.3
  BOTTOM w0.127: v3(22.83,7.9) 23.08,7.65 23.08,5.96 22.84,5.72 22.35,5.72 22.16,5.9 22.16,11.38 21.21,12.34 21.21,18.2 29.56,26.56 29.56,40.19 23.39,46.37 17.3,46.37 16.03,47.64 16.03,49.1 15.02,50.11 15.02,50.31 14.94,50.39 14.74,50.39 14.66,50.47 14.66,50.67 14.58,50.75 14.38,50.75 14.3,50.83 14.3,51.03 14.22,51.11 14.02,51.11 13.94,51.19 13.94,51.39 13.86,51.47 13.66,51.47 13.38,51.75 12.86,51.75 R9.2
FX_N1: length 64.3
  BOTTOM w0.127: v3(20.43,7.9) 20.69,7.64 20.69,6.06 20.43,5.8 20.03,5.8 19.69,6.14 19.69,18.75 27.98,27.05 27.98,28.59 27.42,29.15 27,29.15 26.59,29.56 26.59,30.14 27,30.55 27.42,30.55 27.98,31.11 27.98,31.91 27.42,32.48 27,32.48 26.59,32.89 26.59,33.47 27,33.88 27.42,33.88 27.98,34.44 27.98,35.24 27.42,35.81 27,35.81 26.59,36.21 26.59,36.79 27,37.2 27.42,37.2 28.07,37.86 28.07,38.91 21.73,45.26 16.67,45.26 14.5,47.43 14.5,47.53 14.51,47.54 14.51,47.65 14.44,47.72 14.33,47.72 14.32,47.71 14.22,47.71 14.14,47.78 14.14,47.89 14.15,47.9 14.15,48 14.08,48.08 13.97,48.08 13.96,48.07 13.86,48.07 13.78,48.14 13.78,48.25 13.79,48.26 13.79,48.36 13.72,48.44 13.61,48.44 13.6,48.43 13.5,48.43 13.18,48.74 12.88,48.74 R11.2
FX_N2: length 64.3
  BOTTOM w0.127: v3(18.03,7.9) 18.29,7.64 18.29,6.09 18.06,5.86 17.64,5.86 17.42,6.07 17.42,9.89 16.58,10.72 16.58,23.09 17.2,23.71 22.65,23.71 25.27,26.33 25.27,29.19 24.7,29.75 24.15,29.75 23.74,30.16 23.74,30.74 24.15,31.15 24.7,31.15 25.27,31.72 25.27,32.52 24.7,33.08 24.15,33.08 23.74,33.49 23.74,34.07 24.15,34.48 24.7,34.48 25.27,35.04 25.27,35.84 24.7,36.41 24.15,36.41 23.74,36.82 23.74,37.4 24.15,37.81 24.7,37.81 25.27,38.37 25.27,39.38 21.07,43.58 18.15,43.58 17.32,42.75 14.65,42.75 14.58,42.82 14.58,42.83 14.51,42.9 14.4,42.9 14.33,42.83 14.33,42.82 14.25,42.75 14.15,42.75 14.07,42.82 14.07,42.83 14,42.9 13.89,42.9 13.82,42.83 13.82,42.82 13.74,42.75 13.64,42.75 13.56,42.82 13.56,42.83 13.49,42.9 13.38,42.9 13.31,42.83 13.31,42.82 13.24,42.75 12.86,42.75 R13.2
FX_N3: length 64.3
  BOTTOM w0.127: v3(15.63,7.9) 15.87,7.66 15.87,6.62 15.89,6.6 15.89,6.08 15.59,5.78 15.18,5.78 14.94,6.03 14.94,9.44 13.32,11.06 13.32,22.38 16.66,25.73 20.96,25.73 22.32,27.09 22.32,29.33 21.76,29.89 20.69,29.89 20.28,30.3 20.28,30.88 20.69,31.29 21.76,31.29 22.32,31.86 22.32,32.66 21.76,33.22 20.69,33.22 20.28,33.63 20.28,34.21 20.69,34.62 21.76,34.62 22.32,35.18 22.32,35.98 21.76,36.55 20.69,36.55 20.28,36.96 20.28,37.54 20.69,37.95 21.76,37.95 22.32,38.51 22.32,39.89 20.65,41.57 16.73,41.57 14.91,39.75 14.52,39.75 14.44,39.83 14.44,39.85 14.37,39.92 14.26,39.92 14.19,39.85 14.19,39.83 14.11,39.75 14.01,39.75 13.93,39.83 13.93,39.85 13.86,39.92 13.75,39.92 13.68,39.85 13.68,39.83 13.6,39.75 13.5,39.75 13.43,39.83 13.43,39.85 13.35,39.92 13.25,39.92 13.17,39.85 13.17,39.83 13.1,39.75 12.84,39.75 R15.2
FX_P0: length 64.3
  BOTTOM w0.127: v3(23.63,7.9) 23.35,7.62 23.35,5.85 22.95,5.45 22.24,5.45 21.9,5.79 21.9,11.27 20.94,12.23 20.94,18.31 29.3,26.67 29.3,40.08 23.27,46.1 17.19,46.1 15.77,47.53 15.77,48.99 13.27,51.48 12.85,51.48 12.74,51.37 R8.2
FX_P1: length 64.3
  BOTTOM w0.127: R10.2 12.86,48.48 13.07,48.48 16.55,44.99 21.62,44.99 27.81,38.8 27.81,37.97 27.31,37.47 26.89,37.47 26.33,36.9 26.33,36.1 26.89,35.54 27.31,35.54 27.72,35.13 27.72,34.55 27.31,34.14 26.89,34.14 26.33,33.58 26.33,32.78 26.89,32.21 27.31,32.21 27.72,31.8 27.72,31.22 27.31,30.81 26.89,30.81 26.33,30.25 26.33,29.45 26.89,28.88 27.31,28.88 27.72,28.47 27.72,27.16 19.42,18.86 19.42,6.03 19.92,5.53 20.54,5.53 20.96,5.95 20.96,7.64 v3(21.23,7.9)
FX_P2: length 64.3
  BOTTOM w0.127: R12.2 12.85,42.48 17.43,42.48 18.26,43.31 20.96,43.31 25,39.27 25,38.48 24.59,38.07 24.04,38.07 23.47,37.51 23.47,36.71 24.04,36.14 24.59,36.14 25,35.73 25,35.15 24.59,34.75 24.04,34.75 23.47,34.18 23.47,33.38 24.04,32.81 24.59,32.81 25,32.41 25,31.83 24.59,31.42 24.04,31.42 23.47,30.85 23.47,30.05 24.04,29.49 24.59,29.49 25,29.08 25,26.44 22.54,23.98 17.09,23.98 16.32,23.2 16.32,10.61 17.16,9.78 17.16,5.96 17.53,5.59 18.17,5.59 18.56,5.98 18.56,7.64 v3(18.83,7.9)
FX_P3: length 64.3
  BOTTOM w0.127: R14.2 12.87,39.49 15.02,39.49 16.84,41.3 20.54,41.3 22.06,39.78 22.06,38.62 21.65,38.21 20.58,38.21 20.01,37.65 20.01,36.85 20.58,36.28 21.65,36.28 22.06,35.87 22.06,35.29 21.65,34.88 20.58,34.88 20.01,34.32 20.01,33.52 20.58,32.95 21.65,32.95 22.06,32.54 22.06,31.97 21.65,31.56 20.58,31.56 20.01,30.99 20.01,30.19 20.58,29.63 21.65,29.63 22.06,29.22 22.06,27.2 20.85,26 16.55,26 13.05,22.49 13.05,10.95 14.67,9.33 14.67,5.92 15.07,5.51 15.7,5.51 16.16,5.97 16.16,6.71 16.14,6.73 16.14,7.66 16.25,7.77 16.29,7.77 v3(16.43,7.9)
GP_DIP: length 15.2
  TOP w0.356: SW2.16 R54.1 17.61,77.52 17.56,77.47 R63.1 R100.1 17,82.97 20.35,86.32 20.35,88.39 J16.5
GPIO: length 3.5
  TOP w0.356: J1.34 17.23,15.48 17.25,15.5 XC7.1
I2C_3V3EN: length 99.6
  TOP w0.254: v1(76.37,94.18) 77.35,94.18 U6.6
  TOP w0.356: v1(19.56,75) SW2.15 R55.1
  BOTTOM w0.356: v1(76.37,94.18) 75.63,94.18 69.39,87.94 39,87.94 35.49,91.46 9.49,91.46 7.16,89.13 7.16,84.51 12.74,78.94 12.74,78.87 17.42,74.19 19.1,74.19 19.56,74.65 v1(19.56,75)
I2C_SCL: length 159.2
  TOP w0.127: U1.H1 v2(34.79,45.08)
  TOP w0.356: R76.1 v1(73.76,91.54) ; v1(33.31,31.59) 33.31,30.56 30.05,27.3 26.9,27.3 22.89,23.29 22.89,16.05 23.63,15.32 J1.18 ; v2(34.79,45.08) 34.38,45.08 32.79,46.67 29.63,46.67 v1(27.9,48.41) 18.57,57.74 R3.2 14.78,57.77 14.04,57.77 14.03,57.79 13.14,57.79 12.69,57.33 7.86,57.33 7.18,56.65 7.18,55.09 5.45,53.37 J4.40
  L3_SIG w0.254: J19.2 58.47,84.44 58.47,87.7 59.77,89 59.77,89.99 62.11,92.33 71.23,92.33 72.01,91.54 v1(73.76,91.54) ; v2(34.79,45.08) 34.79,33.12 33.31,31.64 v1(33.31,31.59)
  BOTTOM w0.356: J19.2 59.25,80.33 59.25,76.89 57.87,75.5 52.94,75.5 47.39,69.96 47.39,60.8 42.02,55.44 38.06,55.44 36.86,54.24 30.62,54.24 27.9,51.51 v1(27.9,48.41)
  vias: v3(4.36,53.37)
I2C_SCL_3P3V: length 36.7
  TOP w0.356: R77.2 73.59,95.17 73.6,95.19 U6.1 74.56,98.39 67.85,105.1 52.15,105.1 48.94,108.31 48.94,110.31 J10.1
I2C_SDA: length 157.7
  TOP w0.254: v2(34.38,44.46) 34.79,44.46 U1.J1
  TOP w0.356: R75.1 v1(76.79,91.61) ; J4.39 11.13,54 12.71,55.57 14.16,55.57 14.18,55.54 R4.2 v1(15.63,55.54) 17.13,55.54 v1(27.48,45.19) 28.86,43.81 33.24,43.81 33.89,44.46 v2(34.38,44.46) ; v1(32.46,31.71) 30.46,29.71 28.01,29.71 22.2,23.9 22.2,15.59 22.82,14.97 22.82,12.93 22.83,12.93 J1.20
  L3_SIG w0.254: v2(34.38,44.46) 33.84,43.91 33.84,33.64 32.46,32.26 v1(32.46,31.71) ; v1(76.79,91.61) 76.01,92.38 73.03,92.38 72.02,93.4 61.52,93.4 57.03,88.91 57.03,84.49 J18.2
  BOTTOM w0.356: J18.2 53.04,80.5 53.04,77.94 46.52,71.42 46.52,61.49 42.22,57.19 37.31,57.19 36.07,55.95 27.36,55.95 25.67,54.26 25.67,47.01 v1(27.48,45.19) ; 15.65,55.54 v1(15.63,55.54)
I2C_SDA_3P3V: length 36.7
  TOP w0.356: v1(77.36,95.75) U6.8 78.26,95.19 78.57,95.5 79.29,95.5 R78.2
  BOTTOM w0.356: J10.3 51.51,110.33 51.51,108.7 53.69,106.52 68.37,106.52 77.36,97.53 v1(77.36,95.75)
IFB1: length 96.9
  TOP w0.254: J6.29 63.62,41.72 v1(63.66,41.76)
  TOP w0.356: v1(84.03,95.83) 84.03,92.1 83.44,91.51 83.44,82.91 81.12,80.59 R99.1 78.54,77.05 v1(85.56,71.02) 87.06,71.03 87.66,70.43 J2.31
  L3_SIG w0.254: v1(63.66,41.76) 64.55,41.76 65.63,40.68 67.14,40.68 68.51,42.04 69.92,42.04 70.77,42.89 70.77,53.13 78.11,60.48 79.91,60.48 85.54,66.1 85.56,66.22 v1(85.56,71.02)
  BOTTOM w0.356: J3.11 79.18,110.36 79.18,108.19 84.03,103.34 v1(84.03,95.83)
IFB2: length 116.9
  TOP w0.254: J6.31 63.59,41.22 v1(63.66,41.15) ; R98.1 79.57,81.8 v1(80.29,81.8)
  TOP w0.356: v1(86.29,69.92) J2.32 89.21,69.93 93.66,74.38 93.66,88.62 75.39,106.88 75.39,111.67 J3.10
  L3_SIG w0.254: v1(63.66,41.15) 65.53,39.28 66.83,39.28 68.88,41.33 70.2,41.33 71.46,42.6 71.46,52.44 78.45,59.43 79.95,59.43 86.26,65.74 86.29,65.95 v1(86.29,69.92) 86.29,75.8 v1(80.29,81.8)
IFB3: length 117.9
  TOP w0.254: v1(63.54,40.22) 62.06,40.22 J6.33 ; J2.33 v1(86.96,69.43)
  TOP w0.356: J3.9 76.63,107.65 94.48,89.8 94.48,73.45 90.47,69.43 J2.33 ; R97.1 v1(81.43,83.9)
  L3_SIG w0.254: v1(63.54,40.22) 65.06,38.7 67.31,38.7 69.3,40.68 70.44,40.68 72.25,42.49 72.25,51.99 78.45,58.19 80.62,58.19 81.71,59.27 81.71,60.1 86.96,65.36 v1(86.96,69.43) 86.96,77.17 81.43,82.71 v1(81.43,83.9)
IFB4: length 117.3
  TOP w0.254: J6.35 62.05,39.72 v1(60.41,39.72)
  TOP w0.356: v1(77.33,77.95) 76.23,76.85 76.23,63.75 80.69,59.3 80.69,53.28 85.95,48.01 85.95,38.6 v1(86.62,37.94) 87.14,37.41 J5.31 ; v1(80.54,86.48) 80.54,85.56 R96.1
  BOTTOM w0.356: J3.8 75.3,111.7 75.3,107.83 82.84,100.29 82.84,91.99 80.54,89.7 v1(80.54,86.48) 80.54,85.97 80.54,85.97 80.54,83.41 77.33,80.2 v1(77.33,77.95) ; v1(86.62,37.94) 64.19,37.94 62.41,39.72 v1(60.41,39.72)
IFB5: length 115.9
  TOP w0.254: J6.37 62.05,38.72 v1(60.39,38.72)
  TOP w0.356: v1(76.5,78.17) 75.45,77.12 75.45,63.37 79.73,59.09 79.73,52.94 85.13,47.55 85.13,38.51 v1(86.4,37.24) 86.72,36.91 J5.32 ; R95.1 78.98,90.46 v1(78.96,90.47)
  BOTTOM w0.356: v1(60.39,38.72) 62.2,38.72 63.68,37.24 v1(86.4,37.24) ; J3.7 74.09,106.57 81.78,98.87 81.78,92.42 80.01,90.65 79.14,90.65 v1(78.96,90.47) 78.88,90.39 78.88,88.73 79.82,87.79 79.82,83.9 76.5,80.58 v1(76.5,78.17)
IFB6: length 123.3
  TOP w0.254: J6.39 62.05,38.22 v1(59.86,38.22)
  TOP w0.356: v1(74.51,77.55) 74.51,63.07 78.76,58.82 78.76,52.55 84.16,47.15 84.16,38.45 v1(85.97,36.64) 86.19,36.41 J5.33 ; R94.1 77.84,89.85 v1(77.84,90.49)
  L3_SIG w0.254: v1(77.84,90.49) 75.32,90.49 73.57,88.74 73.57,84.7 72.81,83.93 72.81,79.96 74.51,78.25 v1(74.51,77.55)
  BOTTOM w0.356: v1(59.86,38.22) 61.04,37.04 62.77,37.04 63.17,36.64 v1(85.97,36.64) ; v1(77.84,90.49) 77.84,90.68 78.98,91.82 79.84,91.82 81.03,93 81.03,97.08 72.81,105.3 72.81,111.65 J3.6
IRQ: length 108.2
  TOP w0.254: U1.J9 40.21,44.9 v2(40.21,44.91)
  TOP w0.356: U2.2 TP1.1 48.4,33.55 45.07,33.55 40.26,28.73 36.81,28.73 33.74,25.66 v1(33.74,25.65) ; R70.2 3.31,52.84 2.74,52.26 2.74,25.91 4.53,24.12 14.95,24.12 21.21,17.86 21.21,17.68 21.22,17.67 R16.2 v1(20.48,17.11)
  L3_SIG w0.254: v2(40.21,44.91) 42.8,44.9 48.46,39.24 TP1.1 ; v1(33.74,25.65) 24.03,25.65 20.48,22.1 v1(20.48,17.11)
IRQ_LED: length 1.5
  TOP w0.356: R2.1 D1.1
IRQ_OUT: length 2.6
  TOP w0.356: R1.2 R2.2 54.9,32.96 U2.4
J6_3P3V: length 6.7
  TOP w0.356: R106.2 73.26,42.49 XC12.1 73.19,42.42 R107.2 71.21,42.42 70.04,42.42 69.74,42.72 67.79,42.72 J6.28
J6_26: length 3.6
  TOP w0.254: 69.24,43.22 69.98,43.22 70.39,43.63 70.83,43.63 R107.1
  TOP w0.356: J6.26 67.79,43.22 69.24,43.22
LED9V: length 1.3
  TOP w0.508: R81.1 D3.1
LED_BKLT_EN: length 76.4
  TOP w0.356: J16.3 15.26,88.4 15.26,86.68 13.85,85.27 13.85,78.52 14.9,77.47 R63.2 ; v1(75.01,87.53) U10.15
  BOTTOM w0.356: J16.3 17.26,90.43 35.4,90.43 38.8,87.03 69.94,87.03 70.43,87.53 v1(75.01,87.53)
LED_EN: length 147.4
  TOP w0.254: J6.32 67.79,41.22 v1(66.36,41.22) ; R28.2 R27.2 80.5,69.35 80.51,69.37 v1(80.51,70.05)
  TOP w0.356: J16.8 27.94,81.27 28.56,80.65 28.56,76.42 28.13,75.99 SW2.9 ; R61.1 SW2.9 ; SW2.9 v1(27.18,75.14) ; R50.2 R49.2 81.02,36.31 81,36.33 81,39.1 79.75,40.35 70.1,40.35 69.23,41.22 J6.32
  L3_SIG w0.254: v1(66.36,41.22) 66.36,41.22 67.9,42.75 69.54,42.75 70.08,43.29 70.08,53.72 78.15,61.8 80.33,61.8 82.35,63.83 82.35,69.88 82.17,70.05 v1(80.51,70.05) 79.97,70.6 64.66,70.6 54.82,60.76 31.52,60.76 28.02,64.26 28.02,72.57 27.18,73.41 v1(27.18,75.14)
LVDS_REFCLK: length 21
  L3_SIG w0.254: v1(37.18,24.69) 36.3,24.69 35.59,25.39 35.59,26.22 35.59,26.22 v1(35.59,41.44)
  BOTTOM w0.356: R104.1 v1(35.59,41.44) ; R67.1 38.09,24.7 C55.1 v1(37.18,24.69)
PANEL_3P3V: length 17.4
  TOP w0.254: J5.3 v1(87.06,51.41) ; J5.2 87.09,51.91 v1(86.99,51.82)
  TOP w0.356: R106.1 v1(75.13,43.61)
  BOTTOM w0.508: C12.1 85.96,84.72 C13.1 84.16,84.69 C14.1 83.27,84.71 FB2.2 ; FB3.2 83.47,51.95 C19.1 C18.1 86.21,51.87 C17.1
  BOTTOM w1.016: v1(90.48,84.47) 90.29,84.66 C12.1
  vias: v1(90.05,84.85) v1(90.05,84.48) v1(90.49,84.86) v1(91.59,51.82) v1(91.59,51.4) v1(92.11,51.82) v1(92.11,51.4)
PG: length 80.9
  TOP w0.356: U4.1 4.18,95.42 R103.1 v1(4.17,94.7) ; v1(33.66,57.89) 34.62,57.89 35.66,58.94 R88.1 35.69,61.27 40.99,61.27 42.17,62.45 42.17,68.97 40.74,70.39 R80.1
  BOTTOM w0.356: v1(4.17,94.7) 4.17,94.4 5.58,93 5.58,81.04 15.92,70.69 15.92,63.55 18.17,61.3 27.76,61.3 31.19,57.87 33.63,57.87 v1(33.66,57.89)
PG1P8: length 2.2
  TOP w0.356: U9.9 35.65,62.45 R88.2
PG3P3: length 2.4
  TOP w0.356: U8.9 41.09,74.22 R80.2
PWM1: length 7.4
  TOP w0.356: XC5.1 24.08,16.5 24.66,15.92 26.35,15.92 26.83,15.45 J1.10
PWR_IN: length 15.8
  TOP w0.508: C35.1 v1(22.65,100) ; C35.1 v1(21.59,100.84) ; C35.1 v1(20.47,100) ; v1(25.05,100) C36.1 v1(23.87,100.81) ; R81.2 v1(26,100.64)
  L4_PWR w0.584: SW6.2 30.83,113.64 ; SW6.2 31.81,112.67 ; SW6.2 29.85,112.67 ; SW6.2 30.83,111.69 ; J15.2 30.09,99.96 ; J15.2 28.34,99.96 ; J15.2 29.22,99.09
  BOTTOM w0.508: v1(32.58,98.37) FB5.1 31.74,99.69 v1(30.76,98.71)
PWRIN_SW: length 5.8
  TOP w1.016: D2.1 28.27,112.64 SW6.1
Q1_PIN2: length 8
  TOP w0.356: L1.2 63.31,93.55 62.69,94.18 D5.3 60.02,94.18 59.31,93.47 Q1.3 Q1.2
REFCLK: length 4.7
  TOP w0.076: U1.H2 35.79,45.4 35.55,45.16 35.55,44.79 35.46,44.7 35.46,44.38 v2(35.35,44.27)
  L3_SIG w0.356: v2(35.35,44.27) 36.01,43.62 v1(36.01,43.15)
  BOTTOM w0.356: v1(36.01,43.15) 36.16,43.31 R5.1 36.73,43.29 36.73,43.21 R104.2
RESET#: length 1.5
  TOP w0.356: U3.1 8.7,99.86 R52.2
S_PWMIN: length 168.5
  TOP w0.356: J6.30 69.24,41.72 69.25,41.72 69.77,41.72 70.18,41.31 80.24,41.31 82.15,39.4 82.15,36.33 82.17,36.31 R49.1 86.1,35.68 86.62,35.68 86.89,35.41 J5.35 91.84,35.41 93.24,36.82 93.24,67.03 91.84,68.43 89.22,68.43 89.21,68.43 J2.35 87.26,68.43 86.91,68.78 R27.1 81.66,68.8 v1(81.66,69.5) ; R60.1 SW2.10 v1(25.91,75.02) 25.91,74.74 26.36,74.29 29.45,74.29 30.21,75.05 30.21,88.15 J16.9
  L3_SIG w0.254: v1(81.66,69.5) 79.76,69.5 79.3,69.96 65.4,69.96 55.22,59.78 35.35,59.78 34.28,58.72 31.94,58.72 26.59,64.07 26.59,74.34 v1(25.91,75.02)
SS1P8: length 2.3
  TOP w0.356: U9.15 39.69,68.36 C48.1
SS3P3: length 2.1
  TOP w0.356: U8.15 44.97,79.88 C44.1
TE: length 3.5
  TOP w0.356: J1.38 XC8.1
TEST1: length 53.6
  TOP w0.076: U1.H8 38.78,45.4 v2(38.3,45.89)
  TOP w0.356: v1(30.21,70.74) 30.21,59.38 38.74,50.85 39.41,50.85 v2(40.15,50.11) ; R62.2 v1(22.1,83.23)
  L3_SIG w0.254: v2(38.3,45.89) 38.94,45.89 40.66,47.6 40.66,49.61 40.16,50.11 v2(40.15,50.11)
  BOTTOM w0.356: v1(30.21,70.74) 30.27,70.74 31.07,71.55 31.07,80.66 27.48,84.25 22.66,84.25 22.1,83.69 v1(22.1,83.23)
